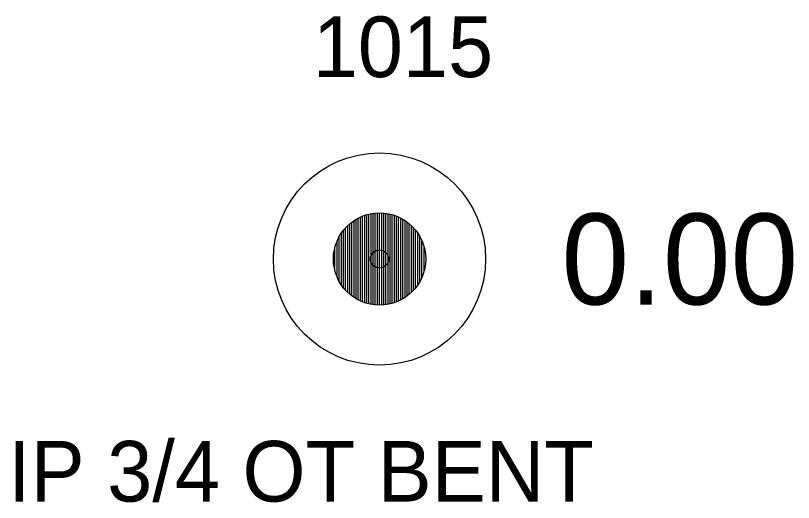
# Model space of a CAD drawing. Extents: x 1664393 to 1667175, y 987029 to 988607.
# Drawn here: x 1664728.23 to 1664741.05, y 987851.98 to 987860.01 of the extents above; entities that cross this region are included whole.
import ezdxf

# ---------------------------------------------------------------- set-up
doc = ezdxf.new("R2010")
doc.units = 0
for name, color, linetype in [('RD_EX_DV_Prop_txCode', 7, 'Continuous'), ('RD_EX_DV_PropPin', 7, 'Continuous'), ('RD_EX_TX_DV_Prop_ELEV', 7, 'Continuous'), ('RD_SMD_Locator', 7, 'Continuous')]:
    doc.layers.add(name, color=color, linetype=linetype)

msp = doc.modelspace()

# ---------------------------------------------------------------- linework, layer by layer
at = {"layer": 'RD_EX_DV_PropPin'}
for p, q in [((1664733.879, 987855.32), (1664733.879, 987856.672)), ((1664733.914, 987855.303), (1664733.914, 987856.689)), ((1664733.949, 987855.288), (1664733.949, 987856.704)), ((1664733.984, 987855.276), (1664733.984, 987856.716)), ((1664734.019, 987855.265), (1664734.019, 987856.727)), ((1664734.054, 987855.255), (1664734.054, 987856.737)), ((1664734.089, 987855.248), (1664734.089, 987856.744)), ((1664734.124, 987855.242), (1664734.124, 987856.75)), ((1664734.159, 987855.238), (1664734.159, 987856.754)), ((1664734.194, 987855.236), (1664734.194, 987856.756)), ((1664734.229, 987855.235), (1664734.229, 987856.757)), ((1664734.264, 987855.236), (1664734.264, 987856.756)), ((1664734.299, 987855.238), (1664734.299, 987856.754)), ((1664734.334, 987855.242), (1664734.334, 987856.75)), ((1664734.369, 987855.248), (1664734.369, 987856.744)), ((1664734.404, 987855.255), (1664734.404, 987856.737)), ((1664734.439, 987855.265), (1664734.439, 987856.727)), ((1664734.474, 987855.276), (1664734.474, 987856.716)), ((1664734.509, 987855.288), (1664734.509, 987856.704)), ((1664734.544, 987855.303), (1664734.544, 987856.689)), ((1664734.579, 987855.32), (1664734.579, 987856.672)), ((1664733.704, 987855.445), (1664733.704, 987856.547)), ((1664733.739, 987855.414), (1664733.739, 987856.578)), ((1664733.774, 987855.386), (1664733.774, 987856.606)), ((1664733.809, 987855.361), (1664733.809, 987856.631)), ((1664733.844, 987855.34), (1664733.844, 987856.652)), ((1664734.614, 987855.34), (1664734.614, 987856.652)), ((1664734.649, 987855.361), (1664734.649, 987856.631)), ((1664734.684, 987855.386), (1664734.684, 987856.606)), ((1664734.719, 987855.414), (1664734.719, 987856.578)), ((1664734.754, 987855.445), (1664734.754, 987856.547)), ((1664733.599, 987855.569), (1664733.599, 987856.423)), ((1664733.634, 987855.522), (1664733.634, 987856.47)), ((1664733.669, 987855.481), (1664733.669, 987856.511)), ((1664734.789, 987855.481), (1664734.789, 987856.511)), ((1664734.824, 987855.522), (1664734.824, 987856.47)), ((1664734.859, 987855.569), (1664734.859, 987856.423)), ((1664733.529, 987855.698), (1664733.529, 987856.294)), ((1664733.564, 987855.626), (1664733.564, 987856.366)), ((1664734.894, 987855.626), (1664734.894, 987856.366)), ((1664734.929, 987855.698), (1664734.929, 987856.294)), ((1664733.494, 987855.8), (1664733.494, 987856.192)), ((1664734.964, 987855.8), (1664734.964, 987856.192))]:
    msp.add_line(p, q, dxfattribs=at)
for radius in [1.75, 0.761]:
    msp.add_circle((1664734.229, 987855.996), radius, dxfattribs=at)
at = {"layer": 'RD_SMD_Locator'}
msp.add_circle((1664734.229, 987855.996), 0.15, dxfattribs=at)

# ---------------------------------------------------------------- texts
at = {"layer": 'RD_EX_DV_Prop_txCode'}
for s, p in [('1015', (1664733.127, 987858.996)), ('IP 3/4 OT BENT', (1664728.103, 987851.996))]:
    msp.add_text(s, height=1, dxfattribs=at).set_placement(p)
at = {"layer": 'RD_EX_TX_DV_Prop_ELEV'}
msp.add_text('0.00', height=1.5, dxfattribs=at).set_placement((1664737.229, 987855.246))

doc.saveas('drawing.dxf')
